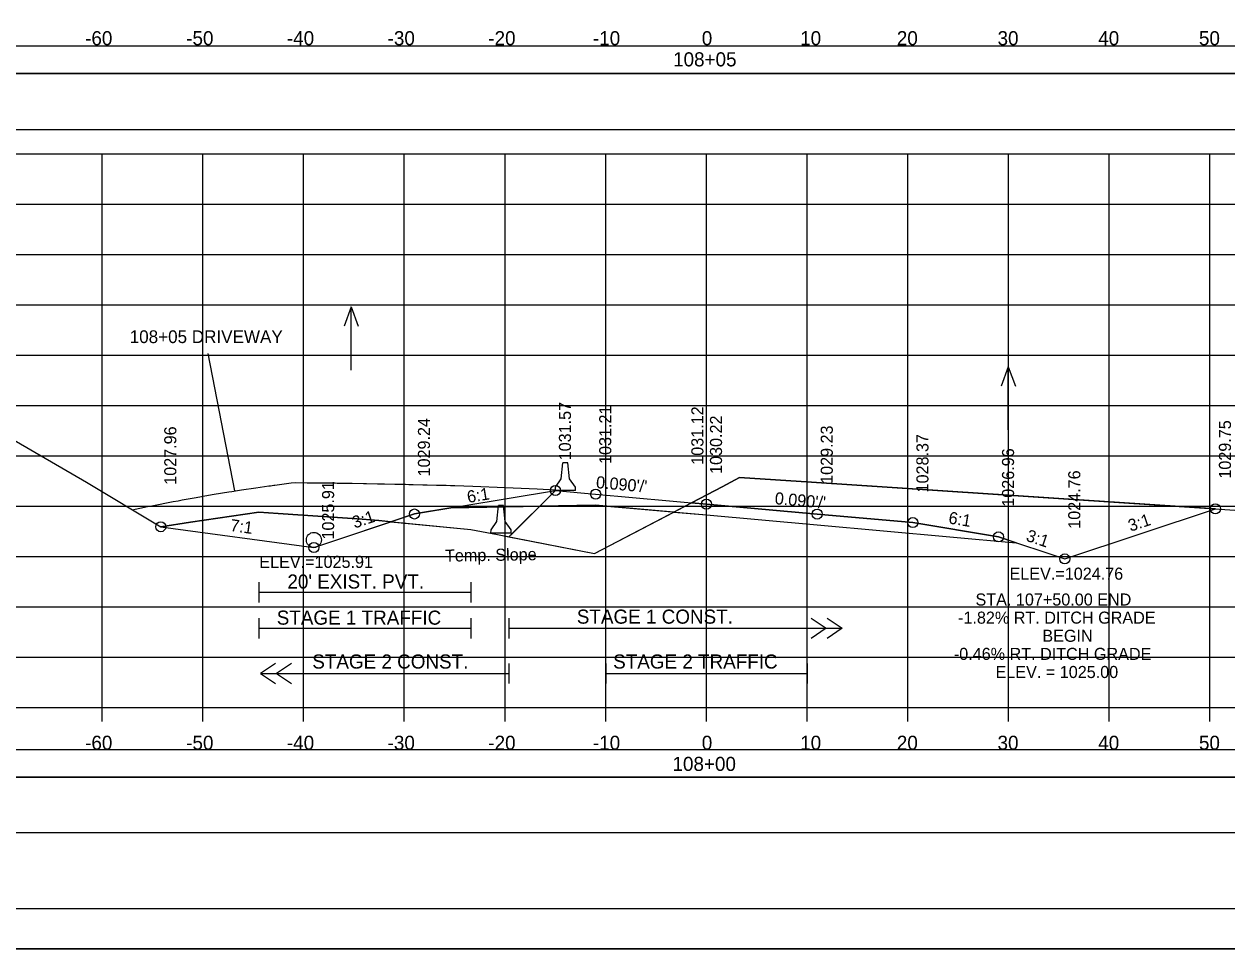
# Model space of a CAD drawing. Extents: x 1370565 to 1374448, y 301010 to 304637.
# Drawn here: x 1370667.3 to 1370786.7, y 302077.2 to 302169.1 of the extents above; entities that cross this region are included whole.
import ezdxf

# ---------------------------------------------------------------- set-up
doc = ezdxf.new("R2010")
doc.units = 0
for name, color, linetype in [('R_Alt Surface', 7, 'Continuous'), ('R_Axis', 7, 'Continuous'), ('R_Axis Annot', 7, 'Continuous'), ('R_Border', 7, 'Continuous'), ('R_Contours', 7, 'Continuous'), ('R_Drive', 7, 'Continuous'), ('R_Exist Surface', 7, 'Continuous'), ('R_Fin Surface', 7, 'Continuous'), ('R_Grid', 7, 'Continuous'), ('R_MOT', 7, 'Continuous'), ('R_No Plot', 7, 'Continuous'), ('R_Water', 7, 'Continuous'), ('R_Water Annot', 7, 'Continuous'), ('R_Xsect Elev', 7, 'Continuous'), ('R_Xsect Slope', 7, 'Continuous')]:
    doc.layers.add(name, color=color, linetype=linetype)

# ---------------------------------------------------------------- blocks, each defined once
blk = doc.blocks.new('MEDBAR_P')
at = {"layer": 'R_MOT'}
for p, q in [((-2.46, -0.98), (-1.63, 6.93)), ((-0.38, 6.93), (-1.63, 6.93)), ((0.87, 6.93), (-0.38, 6.93)), ((1.71, -0.98), (0.87, 6.93)), ((-5.37, -6.81), (-5.34, -5.15)), ((-5.34, -5.15), (-2.46, -0.98)), ((4.66, -5.15), (1.71, -0.98)), ((4.63, -6.81), (4.66, -5.15)), ((4.63, -6.81), (-5.37, -6.81))]:
    blk.add_line(p, q, dxfattribs=at)

msp = doc.modelspace()

# ---------------------------------------------------------------- linework, layer by layer
at = {"layer": 'R_Alt Surface'}
for points in [[(1370709.64, 302121), (1370724.03, 302121.29), (1370735.03, 302120.3), (1370746.03, 302119.31), (1370765.8, 302117.53)], [(1370690.65, 302112.62), (1370711.64, 302112.62)], [(1370715.42, 302110.04), (1370715.42, 302108.04)], [(1370745.42, 302110.04), (1370746.92, 302109.04), (1370745.42, 302108.04)], [(1370747.02, 302110.04), (1370748.52, 302109.04), (1370747.02, 302108.04)], [(1370690.65, 302109.04), (1370711.64, 302109.04)], [(1370715.42, 302109.04), (1370748.52, 302109.04)], [(1370692.24, 302105.56), (1370690.74, 302104.56), (1370692.24, 302103.56)], [(1370693.84, 302105.56), (1370692.34, 302104.56), (1370693.84, 302103.56)], [(1370715.42, 302105.56), (1370715.42, 302103.56)], [(1370725.03, 302105.56), (1370725.03, 302103.56)], [(1370745.03, 302105.56), (1370745.03, 302103.56)], [(1370690.74, 302104.56), (1370715.42, 302104.56)], [(1370725.03, 302104.56), (1370745.03, 302104.56)]]:
    msp.add_lwpolyline(points, dxfattribs=at)
at = {"layer": 'R_Axis'}
for p, q in [((1370585.03, 302101.17), (1370885.03, 302101.17)), ((1370675.03, 302099.77), (1370675.03, 302101.17)), ((1370685.03, 302099.77), (1370685.03, 302101.17)), ((1370695.03, 302099.77), (1370695.03, 302101.17)), ((1370705.03, 302099.77), (1370705.03, 302101.17)), ((1370715.03, 302099.77), (1370715.03, 302101.17)), ((1370725.03, 302099.77), (1370725.03, 302101.17)), ((1370735.03, 302099.77), (1370735.03, 302101.17)), ((1370745.03, 302099.77), (1370745.03, 302101.17)), ((1370755.03, 302099.77), (1370755.03, 302101.17)), ((1370765.03, 302099.77), (1370765.03, 302101.17)), ((1370775.03, 302099.77), (1370775.03, 302101.17)), ((1370785.03, 302099.77), (1370785.03, 302101.17))]:
    msp.add_line(p, q, dxfattribs=at)
for points in [[(1370690.59, 302113.62), (1370690.59, 302111.62)], [(1370711.64, 302113.62), (1370711.64, 302111.62)], [(1370690.59, 302110.04), (1370690.59, 302108.04)], [(1370711.64, 302110.04), (1370711.64, 302108.04)]]:
    msp.add_lwpolyline(points, dxfattribs=at)
at = {"layer": 'R_Border'}
msp.add_line((1370893.21, 302081.17), (1370577.03, 302081.17), dxfattribs=at)
at = {"layer": 'R_Contours'}
for p, q in [((1370733.55, 302121.52), (1370731.79, 302120.59)), ((1370733.55, 302121.52), (1370735.03, 302121.38)), ((1370706.03, 302120.4), (1370703.7, 302119.63)), ((1370709.64, 302121), (1370706.03, 302120.4)), ((1370718.47, 302121.18), (1370709.64, 302121)), ((1370715.42, 302118.13), (1370718.47, 302121.18)), ((1370731.79, 302120.59), (1370735.03, 302120.3)), ((1370703.7, 302119.63), (1370702.49, 302119.74))]:
    msp.add_line(p, q, dxfattribs=at)
for points in [[(1370785.57, 302120.91), (1370745.47, 302123.56), (1370738.32, 302124.03), (1370736.58, 302123.11), (1370733.55, 302121.52)], [(1370765.8, 302117.53), (1370764.03, 302118.12), (1370755.53, 302119.54), (1370746.03, 302120.39), (1370735.03, 302121.38), (1370733.55, 302121.52)], [(1370702.49, 302119.74), (1370700.85, 302119.9), (1370692.51, 302120.46), (1370690.59, 302120.59), (1370683.8, 302119.57), (1370680.84, 302119.13)], [(1370718.47, 302121.18), (1370715.7, 302118.41), (1370715.42, 302118.13)], [(1370715.42, 302118.13), (1370723.91, 302116.46), (1370731.79, 302120.59)], [(1370731.79, 302120.59), (1370724.03, 302121.29), (1370718.47, 302121.18)], [(1370735.03, 302121.38), (1370746.03, 302120.39), (1370755.53, 302119.54), (1370764.03, 302118.12), (1370770.61, 302115.93), (1370785.57, 302120.91)], [(1370735.03, 302120.3), (1370746.03, 302119.31), (1370765.8, 302117.53)], [(1370680.84, 302119.13), (1370696.05, 302117.07), (1370703.7, 302119.63)], [(1370703.7, 302119.63), (1370711.64, 302118.87), (1370714.28, 302118.36), (1370715.42, 302118.13)], [(1370715.42, 302118.13), (1370715.42, 302118.13)], [(1370715.42, 302118.13), (1370715.42, 302118.13)]]:
    msp.add_lwpolyline(points, dxfattribs=at)
at = {"layer": 'R_Drive'}
for points in [[(1370587.98, 302164.18), (1370886.39, 302164.18), (1370886.39, 302166.89), (1370587.98, 302166.89)], [(1370585.82, 302094.26), (1370884.24, 302094.26), (1370884.24, 302096.97), (1370585.82, 302096.97)], [(1370585.82, 302088.74), (1370884.24, 302088.74), (1370884.24, 302094.26), (1370585.82, 302094.26)]]:
    msp.add_lwpolyline(points, close=True, dxfattribs=at)
msp.add_lwpolyline([(1370678.01, 302120.82), (1370679.53, 302121.13), (1370679.94, 302121.21), (1370682.06, 302121.63), (1370682.57, 302121.72), (1370682.97, 302121.79), (1370684.35, 302122.05), (1370685.58, 302122.26), (1370686.16, 302122.36), (1370687.61, 302122.59), (1370687.9, 302122.64), (1370688.45, 302122.73), (1370688.85, 302122.79), (1370690.3, 302123.01), (1370691.56, 302123.19), (1370691.74, 302123.21), (1370692.08, 302123.26), (1370692.18, 302123.27), (1370693.78, 302123.48), (1370693.79, 302123.48), (1370694.19, 302123.52), (1370695.37, 302123.51), (1370695.44, 302123.51), (1370696.89, 302123.49), (1370698.15, 302123.48), (1370698.35, 302123.47), (1370698.38, 302123.47), (1370698.38, 302123.47), (1370698.6, 302123.47), (1370699.85, 302123.45), (1370700.99, 302123.43), (1370701.28, 302123.43), (1370702.37, 302123.41), (1370702.7, 302123.4), (1370703.06, 302123.39), (1370704.1, 302123.37), (1370704.27, 302123.37), (1370704.33, 302123.37), (1370705.16, 302123.35), (1370705.49, 302123.34), (1370705.9, 302123.33), (1370706.87, 302123.31), (1370707.29, 302123.29), (1370708.24, 302123.27), (1370709.18, 302123.25), (1370709.61, 302123.23), (1370709.88, 302123.23), (1370710.03, 302123.22), (1370711.84, 302123.15), (1370715.03, 302123.03), (1370718.22, 302122.89), (1370720.03, 302122.81), (1370720.03, 302122.81), (1370720.03, 302122.81)], dxfattribs=at)
at = {"layer": 'R_Exist Surface'}
msp.add_lwpolyline([(1370585.03, 302144.6), (1370587.71, 302144.4), (1370602.96, 302142.88), (1370604.64, 302142.34), (1370630.92, 302139.15), (1370651.32, 302136.42), (1370673.47, 302123.56), (1370680.84, 302119.13), (1370683.8, 302119.57), (1370690.59, 302120.59), (1370692.51, 302120.46), (1370700.85, 302119.9), (1370702.49, 302119.74), (1370711.64, 302118.87), (1370714.28, 302118.36), (1370723.91, 302116.46), (1370736.58, 302123.11), (1370738.32, 302124.03), (1370745.47, 302123.56), (1370788.49, 302120.72)], dxfattribs=at)
at = {"layer": 'R_Fin Surface'}
msp.add_line((1370720.03, 302122.73), (1370715.42, 302118.13), dxfattribs=at)
msp.add_lwpolyline([(1370588.03, 302158.6), (1370886.45, 302158.6), (1370886.45, 302164.13), (1370588.03, 302164.13)], close=True, dxfattribs=at)
msp.add_lwpolyline([(1370680.84, 302119.13), (1370696.05, 302117.07), (1370706.03, 302120.4), (1370720.03, 302122.73), (1370724.03, 302122.37), (1370735.03, 302121.38), (1370746.03, 302120.39), (1370755.53, 302119.54), (1370764.03, 302118.12), (1370770.61, 302115.93), (1370785.57, 302120.91)], dxfattribs=at)
at = {"layer": 'R_Grid'}
for p, q in [((1370585.03, 302156.17), (1370885.03, 302156.17)), ((1370675.03, 302101.17), (1370675.03, 302156.17)), ((1370685.03, 302101.17), (1370685.03, 302156.17)), ((1370695.03, 302101.17), (1370695.03, 302156.17)), ((1370705.03, 302101.17), (1370705.03, 302156.17)), ((1370715.03, 302101.17), (1370715.03, 302156.17)), ((1370725.03, 302101.17), (1370725.03, 302156.17)), ((1370735.03, 302101.17), (1370735.03, 302156.17)), ((1370745.03, 302101.17), (1370745.03, 302156.17)), ((1370755.03, 302101.17), (1370755.03, 302156.17)), ((1370765.03, 302101.17), (1370765.03, 302156.17)), ((1370775.03, 302101.17), (1370775.03, 302156.17)), ((1370785.03, 302101.17), (1370785.03, 302156.17)), ((1370585.03, 302151.17), (1370885.03, 302151.17)), ((1370585.03, 302146.17), (1370885.03, 302146.17)), ((1370585.03, 302141.17), (1370885.03, 302141.17)), ((1370585.03, 302136.17), (1370885.03, 302136.17)), ((1370585.03, 302131.17), (1370885.03, 302131.17)), ((1370585.03, 302126.17), (1370885.03, 302126.17)), ((1370585.03, 302121.17), (1370885.03, 302121.17)), ((1370585.03, 302116.17), (1370885.03, 302116.17)), ((1370585.03, 302111.17), (1370885.03, 302111.17)), ((1370585.03, 302106.17), (1370885.03, 302106.17)), ((1370585.03, 302101.17), (1370885.03, 302101.17))]:
    msp.add_line(p, q, dxfattribs=at)
at = {"layer": 'R_No Plot'}
msp.add_line((1370564.63, 302077.19), (1370897.96, 302077.19), dxfattribs=at)
for points in [[(1370564.62, 302290.52), (1370897.96, 302290.52), (1370897.96, 302077.18), (1370564.62, 302077.18)], [(1370810.95, 302286.63), (1370830.57, 302286.63), (1370830.57, 302276.75), (1370846.68, 302276.75), (1370869.88, 302276.75), (1370869.88, 302244.08), (1370893.09, 302244.08), (1370893.21, 302081.17), (1370577.03, 302081.17), (1370577.03, 302286.63)]]:
    msp.add_lwpolyline(points, close=True, dxfattribs=at)
for centre in [(1370720.03, 302122.73), (1370724.03, 302122.37), (1370735.03, 302121.38), (1370706.03, 302120.4), (1370746.03, 302120.39), (1370785.57, 302120.91), (1370680.84, 302119.13), (1370755.53, 302119.54), (1370764.03, 302118.12), (1370696.05, 302117.07), (1370770.61, 302115.93)]:
    msp.add_circle(centre, 0.5, dxfattribs=at)
at = {"layer": 'R_Water'}
msp.add_circle((1370696.05, 302117.82), 0.75, dxfattribs=at)
at = {"layer": 'R_Water Annot'}
for p, q in [((1370699.75, 302140.97), (1370699.05, 302139.05)), ((1370699.75, 302134.69), (1370699.75, 302140.97)), ((1370699.75, 302140.97), (1370700.45, 302139.05)), ((1370685.53, 302136.34), (1370688.15, 302122.69)), ((1370765.01, 302135.03), (1370764.31, 302133.11)), ((1370765.01, 302128.75), (1370765.01, 302135.03)), ((1370765.01, 302135.03), (1370765.71, 302133.11))]:
    msp.add_line(p, q, dxfattribs=at)
at = {"layer": 'R_Xsect Elev'}
msp.add_line((1370735.03, 302122.29), (1370735.03, 302132.29), dxfattribs=at)

# ---------------------------------------------------------------- block references
at = {"layer": 'R_Fin Surface', "xscale": 0.2, "yscale": 0.20000000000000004}
for p in [(1370721.1, 302124.1), (1370714.71, 302119.85)]:
    msp.add_blockref('MEDBAR_P', p, dxfattribs=at)

# ---------------------------------------------------------------- texts
at = {"layer": 'R_Axis Annot'}
for s, p in [('-60', (1370673.33, 302166.97)), ('-50', (1370683.37, 302166.97)), ('-40', (1370693.37, 302166.97)), ('-30', (1370703.37, 302166.97)), ('-20', (1370713.37, 302166.97)), ('-10', (1370723.76, 302166.97)), ('0', (1370734.57, 302166.97)), ('10', (1370744.34, 302166.97)), ('20', (1370753.94, 302166.97)), ('30', (1370763.94, 302166.97)), ('40', (1370773.94, 302166.97)), ('50', (1370783.94, 302166.97)), ('108+05', (1370731.72, 302164.87)), ("20' EXIST. PVT.", (1370693.42, 302112.99)), ('-60', (1370673.33, 302096.97)), ('-50', (1370683.37, 302096.97)), ('-40', (1370693.37, 302096.97)), ('-30', (1370703.37, 302096.97)), ('-20', (1370713.37, 302096.97)), ('-10', (1370723.76, 302096.97)), ('0', (1370734.57, 302096.97)), ('10', (1370744.34, 302096.97)), ('20', (1370753.94, 302096.97)), ('30', (1370763.94, 302096.97)), ('40', (1370773.94, 302096.97)), ('50', (1370783.94, 302096.97)), ('108+00', (1370731.66, 302094.87))]:
    msp.add_text(s, height=1.4, dxfattribs=at).set_placement(p)
at = {"layer": 'R_Water'}
for s, p in [('STAGE 1 TRAFFIC', (1370692.36, 302109.4)), ('STAGE 1 CONST.', (1370722.16, 302109.5)), ('STAGE 2 CONST.', (1370695.89, 302105.04)), ('STAGE 2 TRAFFIC', (1370725.77, 302105.04))]:
    msp.add_text(s, height=1.4, dxfattribs=at).set_placement(p)
at = {"layer": 'R_Water Annot'}
msp.add_text('108+05 DRIVEWAY', height=1.2661, dxfattribs=at).set_placement((1370677.76, 302137.38))
at = {"layer": 'R_Xsect Elev'}
for s, p in [('1031.57', (1370721.58, 302125.73)), ('1031.21', (1370725.58, 302125.37)), ('1031.12', (1370734.73, 302125.29)), ('1029.24', (1370707.58, 302124.13)), ('1030.22', (1370736.58, 302124.38)), ('1027.96', (1370682.39, 302123.3)), ('1029.23', (1370747.58, 302123.39)), ('1029.75', (1370787.12, 302123.91)), ('1028.37', (1370757.08, 302122.54)), ('1026.96', (1370765.58, 302121.12)), ('1024.76', (1370772.16, 302118.93)), ('1025.91', (1370698.06, 302117.86))]:
    msp.add_text(s, height=1.2, rotation=90, dxfattribs=at).set_placement(p)
for s, p in [('ELEV.=1025.91', (1370690.63, 302115.04)), ('ELEV.=1024.76', (1370765.13, 302113.87)), ('STA. 107+50.00 END', (1370761.75, 302111.3)), ('-1.82% RT. DITCH GRADE', (1370760.02, 302109.5)), ('BEGIN', (1370768.39, 302107.7)), ('-0.46% RT. DITCH GRADE', (1370759.6, 302105.9)), ('ELEV. = 1025.00', (1370763.74, 302104.1))]:
    msp.add_text(s, height=1.2, dxfattribs=at).set_placement(p)
at = {"layer": 'R_Xsect Slope'}
for s, rotation, p in [("0.090'/'", 354.8572, (1370724.03, 302122.98)), ('6:1', 9.4623, (1370711.36, 302121.49)), ("0.090'/'", 354.8572, (1370741.78, 302121.38)), ('3:1', 18.4349, (1370700.09, 302118.95)), ('6:1', 350.5377, (1370759.01, 302119.47)), ('3:1', 18.4332, (1370777.14, 302118.63)), ('7:1', 352.3192, (1370687.69, 302118.71)), ('3:1', 341.5651, (1370766.69, 302117.76)), ('Temp. Slope', 0.936, (1370709.08, 302115.66))]:
    msp.add_text(s, height=1.2, rotation=rotation, dxfattribs=at).set_placement(p)

doc.saveas('drawing.dxf')
